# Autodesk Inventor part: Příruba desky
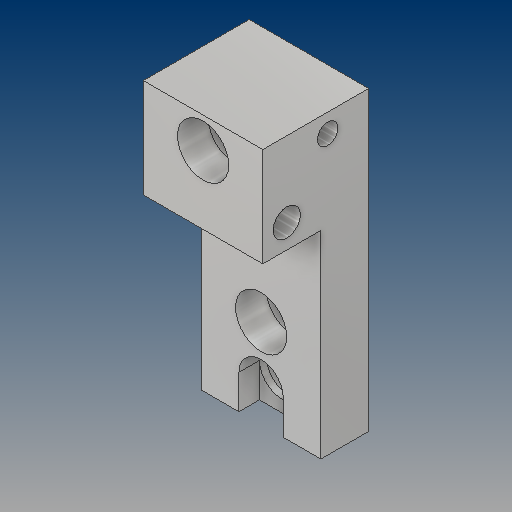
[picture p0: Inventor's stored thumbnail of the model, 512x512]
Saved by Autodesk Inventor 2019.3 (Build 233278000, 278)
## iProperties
Created: 2019-01
Part Number: Příruba desky
Material: Hliník 6061-AHC
Document SubType Name: Modeling
Designer: B-hon
Density: 2.7 g/cm^3
Appearance: Hliník – tmavý
Stock Number: 19-A3-P-22
Mass: 139.604 g
Surface Area: 142.396 cm^2
Volume: 51.7052 cm^3
Author: B-hon
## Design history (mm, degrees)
sketch "Náčrt1"
  geometry: L1 (-32.5, 40)-(32.5, 40); L2 (32.5, 40)-(32.5, -40); L3 (32.5, -40)-(-32.5, -40); L4 (-32.5, -40)-(-32.5, 40); L5 (-32.5, 40)-(32.5, -40); L6 (32.5, 40)-(-32.5, -40); 1 further point
  constraints: 12 end point, 2 midpoint, 2 parallel, 1 horizontal, 1 perpendicular
  dimensions: "d0" = 65 distance of L2.end L3.end; "d1" = 80 distance of L1.end L2.end
extrude "Vysunutí1" new body sketch "Náčrt1" distance "d2" = 26; taper "d3" = 0 deg
sketch "Náčrt2"
  geometry: L1 (-44.381, 28)-(47.748, 28); L2 (47.748, 28)-(47.748, 22); L3 (47.748, 22)-(-44.381, 22); L4 (-44.381, 22)-(-44.381, 28); L5 (-44.381, 28)-(47.748, 22); L6 (47.748, 28)-(-44.381, 22); L7 (-32.5, -40)-(32.5, -40) reference; L8 (-38.512, 18)-(43.239, 18); L9 (43.239, 18)-(43.239, -45.522); L10 (43.239, -45.522)-(-38.512, -45.522); L11 (-38.512, -45.522)-(-38.512, 18); L12 (-32.5, 40)-(-32.5, -40) reference; 2 further points
  constraints: 20 end point, 4 parallel, 2 horizontal, 2 midpoint, 2 perpendicular
  dimensions: "d4" = 6 distance of L1.end L2.end; "d5" = 65 distance from line of L7 point (1.683, 25); "d6" = 7 distance from line of L8 point (1.683, 25)
extrude "Vysunutí2" cut sketch "Náčrt2" distance "d10" = 14; taper "d11" = 0 deg
sketch "Náčrt3"
  geometry: L1 (-39.607, 44.84)-(-17.5, 44.84); L2 (-17.5, 44.84)-(-17.5, 11.926); L3 (-17.5, 11.926)-(-39.607, 11.926); L4 (-39.607, 11.926)-(-39.607, 44.84); L5 (17.5, 44.045)-(36.686, 44.045); L6 (36.686, 44.045)-(36.686, 9.931); L7 (36.686, 9.931)-(17.5, 9.931); L8 (17.5, 9.931)-(17.5, 44.045); L9 (-32.5, 40)-(-32.5, 18) reference; 1 further point
  constraints: 16 end point, 4 parallel, 2 horizontal, 2 perpendicular
  dimensions: "d12" = 35 distance between parallel lines of L8 L2; "d13" = 15 distance between parallel lines of L9 L2
extrude "Vysunutí3" cut sketch "Náčrt3" distance "d14" = 14; taper "d15" = 0 deg
node "Upravit přímo1"
sketch "Náčrt6"
  geometry: L1 (32.5, -40)-(-32.5, -40) reference; C1 r 6.5 at (0, -30); 1 further point
  constraints: 1 centre point
  dimensions: "d39" = 13 diameter of C1; "d40" = 10 distance from line of L1 C1.centre
extrude "Vysunutí4" cut sketch "Náčrt6" distance "d41" = 8; taper "d42" = 0 deg
sketch "Náčrt7"
  geometry: L1 (-6.5, -60.947)-(6.5, -60.947); L2 (6.5, -60.947)-(6.5, -30); L3 (6.5, -30)-(-6.5, -30); L4 (-6.5, -30)-(-6.5, -60.947); L5 (-6.5, -60.947)-(6.5, -30); L6 (6.5, -60.947)-(-6.5, -30); C1 r 6.5 at (0, -30) reference; 2 further points
  constraints: 12 end point, 2 midpoint, 2 parallel, 1 horizontal, 1 perpendicular
  dimensions: "d43" = 13 distance of L3.end L2.end; "d98" = 0 distance from line of C1.centre L3; "d99" = 6.5 distance from line of C1.centre L4
extrude "Vysunutí5" cut sketch "Náčrt7" distance "d44" = 6; taper "d45" = 0 deg
node "Upravit přímo2"
sketch "Náčrt9"
  geometry: L1 (17.5, 18)-(17.5, 45) reference; L2 (-6.5, -40)-(-32.5, -40) reference; 2 further points
  dimensions: "d58" = 17.5 distance from line of L1 point (0, -14); "d59" = 26 distance from line of L2 point (0, -14)
hole "Díra4" sketch "Náčrt9" at (0, -14) diameter "d60" = 8.4; stored, may be unused: countersink angle "d64" = 90 deg, drill point angle "d66" = 118 deg; dims "d61" = 16, "d62" = 15, "d63" = 9, "d65" = 8
sketch "Náčrt10"
  geometry: L1 (-48.128, 53.565)-(-17.5, 53.565); L2 (-17.5, 53.565)-(-17.5, -46.218); L3 (-17.5, -46.218)-(-48.128, -46.218); L4 (-48.128, -46.218)-(-48.128, 53.565); L5 (17.5, 54.3)-(38.723, 54.3); L6 (38.723, 54.3)-(38.723, -45.483); L7 (38.723, -45.483)-(17.5, -45.483); L8 (17.5, -45.483)-(17.5, 54.3); L9 (-17.5, 45)-(-17.5, 18) reference; L10 (17.5, 18)-(17.5, 45) reference; 1 further point
  constraints: 16 end point, 4 parallel, 2 horizontal, 2 perpendicular
  dimensions: "d67" = 0 distance between parallel lines of L9 L2; "d68" = 0 distance between parallel lines of L8 L10
extrude "Vysunutí6" cut sketch "Náčrt10" distance "d69" = 15; taper "d70" = 0 deg
node "Upravit přímo4"
sketch "Náčrt11"
  geometry: L1 (35, 29)-(0, 29) reference; L2 (35, 0)-(35, 29) reference; 2 further points
  dimensions: "d77" = 9 distance from line of L1 point (17.5, 20); "d78" = 17.5 distance from line of L2 point (17.5, 20)
hole "Díra5" sketch "Náčrt11" at (17.5, 20) diameter "d79" = 8.4; stored, may be unused: countersink angle "d83" = 90 deg, drill point angle "d85" = 118 deg; dims "d80" = 16, "d81" = 15, "d82" = 9, "d84" = 8
node "Upravit přímo5"
sketch "Náčrt12"
  geometry: L1 (14, 87)-(14, 0) reference; L2 (-17, 87)-(14, 87) reference; 2 further points
  dimensions: "d89" = 12 distance from line of L1 point (2, 81.5); "d90" = 5.5 distance from line of L2 point (2, 81.5)
hole "Díra6" sketch "Náčrt12" at (2, 81.5) diameter "d91" = 6; stored, may be unused: countersink angle "d95" = 90 deg, drill point angle "d97" = 118 deg; dims "d92" = 16, "d93" = 15, "d94" = 9, "d96" = 10
sketch "Náčrt13"
  geometry: L1 (-17, 58)-(-17, 87) reference; L2 (0, 58)-(-17, 58) reference; 2 further points
  dimensions: "d101" = 7 distance from line of L1 point (-10, 65); "d102" = 7 distance from line of L2 point (-10, 65)
hole "Díra7" sketch "Náčrt13" at (-10, 65) diameter "d103" = 8; stored, may be unused: countersink angle "d107" = 90 deg, drill point angle "d109" = 118 deg; dims "d104" = 6, "d105" = 4, "d106" = 2, "d108" = 10
node "Těleso1"
feature "Posunout1" dims "d27" = 5
feature "Posunout2" dims "d48" = 3
feature "Posunout4" dims "d76" = 2
feature "Posunout5" dims "d88" = 2
other parameters: "d25" = 0, "d26" = 0, "d46" = 0, "d47" = 0, "d74" = 0, "d75" = 0, "d86" = 0, "d87" = 0
